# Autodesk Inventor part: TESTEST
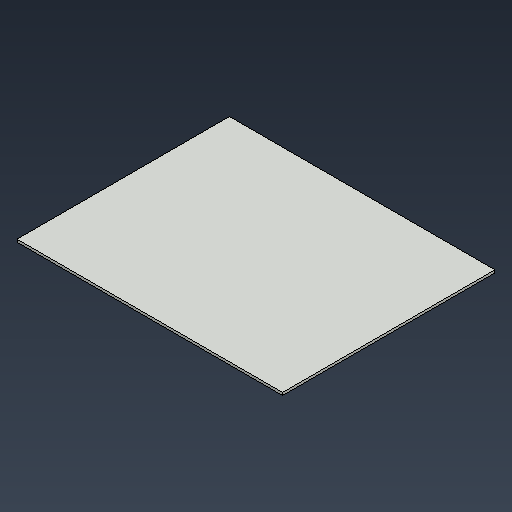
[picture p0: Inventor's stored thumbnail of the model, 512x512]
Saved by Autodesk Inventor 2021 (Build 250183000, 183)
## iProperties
Manager: =<Keywords> <Authority> <Part number>
Created: 2019-12
Part Number: TESTEST
Project: projekt
Material: S355
Description: P 0,5x20,9x33,3
Document SubType Name: Sheet Metal
Designer: naus
Authority: cislo projektu
Stock Number: norma
Density: 7.8 g/cm^3
Sheet Metal Rule: Default_mm
Appearance: RAL7038
Flat Pattern Width: 4 cm
Flat Pattern Length: 5 cm
Flat Pattern Area: 20 cm^2
Sheet Metal Width: 40,000 mm
Sheet Metal Length: 50,000 mm
Sheet Metal Area: 2000,000 mm^2
Mass: 7.8 g
Surface Area: 40.9 cm^2
Volume: 1 cm^3
SM_Thickness: 0,5
SM_Length: 50
SM_Width: 40
SM_Extents: 50x40
HEIGHT: 0.5
WIDTH: 20.9
LENGTH: 33.3
a24_Objem_Media: ne
Volume_Fluid_Category: NO
Title: nazov
Subject: material
Author: naus
Keywords: 27
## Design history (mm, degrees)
node "Face1"
  sketch "Sketch1"
    geometry: L1 (-25, 20)-(25, 20); L2 (25, 20)-(25, -20); L3 (25, -20)-(-25, -20); L4 (-25, -20)-(-25, 20); L5 (-25, 20)-(25, -20); L6 (25, 20)-(-25, -20); 1 further point
    constraints: 12 end point, 2 midpoint, 2 parallel, 1 horizontal, 1 perpendicular
    dimensions: "d3" = 50 distance of L2.end L3.end; "d4" = 40 distance of L1.end L2.end
body "Solid1"
face "Plate1" dims "d0" = 0.5 (= Thickness)
feature "Definition1"
other parameters: "Pipe_Thickness_tl" = 5 [user parameter], "Thickness" = 0.5 (derived), "KFactor" = 4.4, "BendRadius" = 0.5 (= Thickness), "BendReliefWidth" = 0.5 (= Thickness), "BendReliefDepth" = 0.25 (= 0.5 x Thickness), "CornerReliefSize" = 2 (= 4 x Thickness), "SeamGap" = 0.01, "MinimumRemnant" = 1 (= 2 x Thickness), "TransitionRadius" = 0.5 (= BendRadius), "JacobiRadiusSize" = 0.5 (= BendRadius), "GapSize" = 0.5 (= Thickness), "Pipe_Thickness_tl" = 5, "BendRadius" = 0.5, "BendReliefDepth" = 0.25, "BendReliefWidth" = 0.5, "CornerReliefSize" = 2, "GapSize" = 0.5, "JacobiRadiusSize" = 0.5, "MinimumRemnant" = 1, "Thickness" = 0.5, "TransitionRadius" = 0.5
